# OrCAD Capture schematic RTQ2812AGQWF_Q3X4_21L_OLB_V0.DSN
size A2; note: Edison; note: RTQ2820_Q3X4_21L_ENG_V0
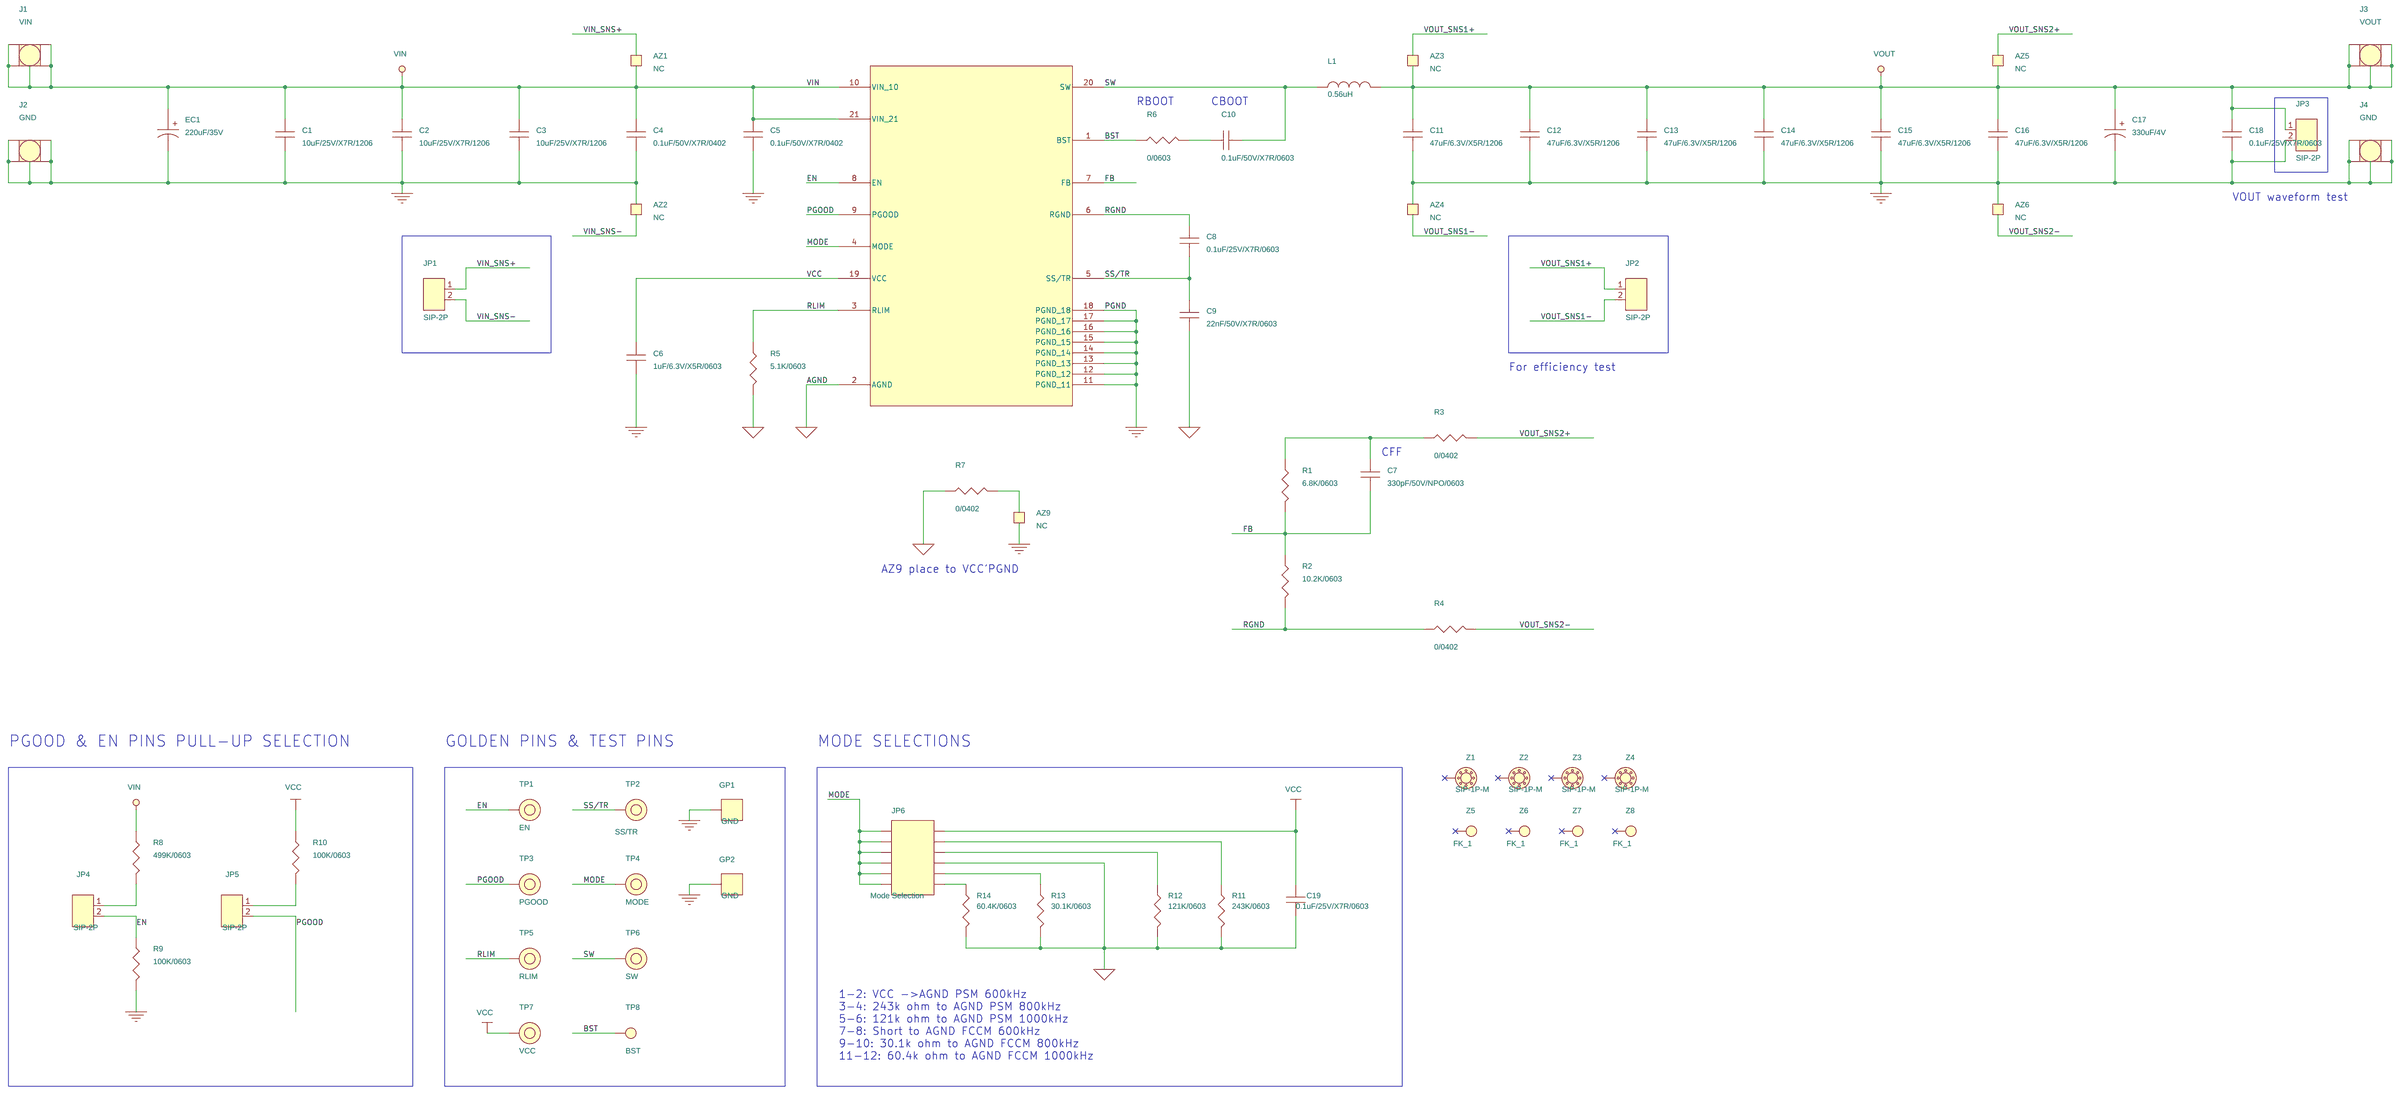
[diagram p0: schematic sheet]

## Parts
AZ1  NC  [nc-short10x30mil]
AZ2  NC  [nc-short10x30mil]
AZ3  NC  [nc-short10x30mil]
AZ4  NC  [nc-short10x30mil]
AZ5  NC  [nc-short10x30mil]
AZ6  NC  [nc-short10x30mil]
AZ9  NC  [nc-short10x30mil]
C1  10uF/25V/X7R/1206  [C-1206]
C2  10uF/25V/X7R/1206  [C-1206]
C3  10uF/25V/X7R/1206  [C-1206]
C4  0.1uF/50V/X7R/0402  [C-0402]
C5  0.1uF/50V/X7R/0402  [C-0402]
C6  1uF/6.3V/X5R/0603  [C-0603]
C7  330pF/50V/NPO/0603  [C-0603]
C8  0.1uF/25V/X7R/0603  [C-0603]
C9  22nF/50V/X7R/0603  [C-0603]
C10  0.1uF/50V/X7R/0603  [C-0603]
C11  47uF/6.3V/X5R/1206  [C-1206]
C12  47uF/6.3V/X5R/1206  [C-1206]
C13  47uF/6.3V/X5R/1206  [C-1206]
C14  47uF/6.3V/X5R/1206  [C-1206]
C15  47uF/6.3V/X5R/1206  [C-1206]
C16  47uF/6.3V/X5R/1206  [C-1206]
C17  330uF/4V  [c-1206-d3]
C18  0.1uF/25V/X7R/0603  [C-0603]
C19  0.1uF/25V/X7R/0603  [C-0603]
EC1  220uF/35V  [EC-2P_10_5MM]
GP1  GND  [SIP-1P-GP]
GP2  GND  [SIP-1P-GP]
J1  VIN  [SIP-5P_PW_L]
J2  GND  [SIP-5P_PW_L]
J3  VOUT  [SIP-5P_PW_L]
J4  GND  [SIP-5P_PW_L]
JP1  SIP-2P  [SIP-2P]
JP2  SIP-2P  [SIP-2P]
JP3  SIP-2P  [SIP-2P]
JP4  SIP-2P  [SIP-2P]
JP5  SIP-2P  [SIP-2P]
JP6  Mode Selection  [HEADER6X2]
L1  0.56uH  [L-11-5X10]
R1  6.8K/0603  [R-0603]
R2  10.2K/0603  [R-0603]
R3  0/0402  [R-0402]
R4  0/0402  [R-0402]
R5  5.1K/0603  [R-0603]
R6  0/0603  [R-0603]
R7  0/0402  [R-0402]
R8  499K/0603  [R-0603]
R9  100K/0603  [R-0603]
R10  100K/0603  [R-0603]
R11  243K/0603  [R-0603]
R12  121K/0603  [R-0603]
R13  30.1K/0603  [R-0603]
R14  60.4K/0603  [R-0603]
TP1  EN  [SIP-1P-TP]
TP2  SS/TR  [SIP-1P-TP]
TP3  PGOOD  [SIP-1P-TP]
TP4  MODE  [SIP-1P-TP]
TP5  RLIM  [SIP-1P-TP]
TP6  SW  [SIP-1P-TP]
TP7  VCC  [SIP-1P-TP]
TP8  BST  [FK_1]
U1  IC-4X2  [qfn3x4_21l_mpq8634a_moq8633b]
Z1  SIP-1P-M  [SIP-1P-M]
Z2  SIP-1P-M  [SIP-1P-M]
Z3  SIP-1P-M  [SIP-1P-M]
Z4  SIP-1P-M  [SIP-1P-M]
Z5  FK_1  [FK_1]
Z6  FK_1  [FK_1]
Z7  FK_1  [FK_1]
Z8  FK_1  [FK_1]

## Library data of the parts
AZ1-AZ6 AZ9 = T_POINT_S: Short Pin 10X30mil; currency: NTD; maker_part_number: NC-SHORT_10X30MIL; notes: S1_IAD1; package: 10X30mil; part_number: NC-SHORT_10X30MIL; part_type: SHORT; price: 0; Datasheet: IO.pdf
C1-C3 = CAP: CAP CER 10uF 25V X7R 1206; FPLIST: C-1206,N_C1206_INTEL,C-1206_INTEL,C-1206_AD; currency: USD; maker: TAIYO YUDEN; maker_part_number: TMK316AB7106KL-T; notes: E1_IAD1; package: 1206; part_number: TMK316AB7106KL-T; part_type: Ceramic; price: 0.0294; size: 3.20X1.60X0.95 mm; Datasheet: TMK316AB7106KL-T.pdf
C4 C5 = CAP: CAP CER 0.1uF(100nF)50V X7R 0402; FPLIST: C-0402,C0402,C-0402_ADPS; currency: USD; maker: WALSIN; maker_part_number: 0402B104K500CT; notes: E1_IAD1_WALSIN-0402B104K500CT; package: 0402; part_number: 0402B104K500CT; part_type: Ceramic; price: 0.0048; size: 1.00x0.50x0.55 mm; Datasheet: 0402B104K500CT.pdf
C6 = CAP: CAP CER 1uF 6.3V X5R 0603; FPLIST: C-0603,N_C0603_INTEL,C-0603_INTEL,C-0603_AD,0603C,C-0603_ADPS; currency: NTD; maker: MURATA; maker_part_number: GRM188R60J105KA01D; notes: C1_IAD1; package: 0603; part_number: GRM188R60J105KA01D; part_type: Ceramic; price: 5; size: 1.60X0.80X0.80mm; specific_part_bu: Specific-CP; supplier: NA; vendor: NA; Datasheet: cap_0603_1uF6.3V.pdf
C7 = CAP: 0603 NPO 330pF 50V; FPLIST: C-0603,N_C0603_INTEL,C-0603_INTEL,C-0603_AD,0603C,C-0603_ADPS; currency: USD; maker: WALSIN; maker_part_number: 0603N331J500CT; notes: E1_IAD1_Old:0603N331J500LT; package: 0603; part_number: 0603N331J500CT; part_type: Ceramic; price: 0.001800; size: 1.60x0.80x0.87 mm; Datasheet: ASC_General_Purpose.pdf
C8 C19 = CAP: CAP CER 0.1uF 25V X7R 0603; FPLIST: C-0603,N_C0603_INTEL,C-0603_INTEL,C-0603_AD,0603C; currency: USD; maker: WALSIN; maker_part_number: 0603B104K250CT; notes: E1_IAD1_WALSIN-0603B104K250CT=> Suggest using the  0402B104K250CT; package: 0603; part_number: 0603B104K250CT; part_type: Ceramic; price: 0.0019; size: 1.60x0.80x0.80 mm; specific_part_bu: Specific; Datasheet: 0603B104K250CT.pdf
C9 = CAP: CAP CER 22nF/50V/X7R/0603; FPLIST: C-0603,N_C0603_INTEL,C-0603_INTEL,C-0603_AD,0603C,C-0603_ADPS; currency: USD; maker: MURATA; maker_part_number: GRM188R71H223KA01D; notes: C1_IAD1_Suggest using alternative matericals-GRM155R71H223KA12D; package: 0603; part_number: GRM188R71H223KA01D; part_type: Ceramic; price: 0.003; size: 1.60x0.80x0.80 mm; supplier: MURATA; vendor: MURATA; Datasheet: GRM188R71H223KA01D.pdf
C10 = CAP: CAP CER 0.1uF 50V X7R 0603; FPLIST: C-0603,N_C0603_INTEL,C-0603_INTEL,C-0603_AD,0603C,C-0603_ADPS; currency: USD; maker: MURATA; maker_part_number: GRM188R71H104KA93D; notes: C1_IAD1_WALSIN-0603B104K500CT=>???0402B104K500CT; package: 0603; part_number: GRM188R71H104KA93D; part_type: Ceramic; price: 0.0048; size: 1.60x0.80x0.80 mm; Datasheet: GRM188R71H104KA93D.pdf
C11-C16 = CAP: CAP CER 47uF 6.3V X5R 1206; FPLIST: C-1206,N_C1206_INTEL,C-1206_INTEL,C-1206_AD,C-1206-D3; currency: USD; maker: TDK; maker_part_number: C3216X5R0J476M160AC; notes: S1_IAD1_EOL,P/N is corresponding for WALSIN-1206X476M6R3CT-USD-0.03240-1KK BOM COST; package: 1206; part_number: C3216X5R0J476M160AC; part_type: Ceramic; price: 0.03240; size: 3.20x1.60x1.60 mm; Datasheet: mlcc_commercial_general_en.pdf
C17 = CAP-POL: Polymer Alum Cap 330uF 20% 4V; currency: NTD; maker: PANASONIC; maker_part_number: EEFSX0G331ER; notes: E1_IAD1_Free_Sample; package: SP-CAP; part_number: EEFSX0G331ER; part_type: POS; price: 0; size: 7.30x4.30x1.90 mm; specific_part_bu: Specific-CP; Datasheet: EEFSX0G331ER.pdf
C18 = CAP: CAP, CERM, 0.1uF, 25V, +/- 10%, X7R,0603; FPLIST: C-0603,N_C0603_INTEL,C-0603_INTEL,C-0603_AD,0603C; currency: NTD; maker: MURATA; maker_part_number: GRM188R71E104KA01D; notes: C1_IAD1; package: 0603; part_number: GRM188R71E104KA01D; part_type: Ceramic; price: 0.01; size: 1.6X0.8X0.8 mm; specific_part_bu: Specific-MB; Datasheet: GRM188R71E104KA01-01.pdf
EC1 = CAP-POL: E CAP ALUM 220uF 20% 35V RADIAL; currency: NTD; maker: RUBYCON; maker_part_number: 35YXG220MEFC10X12.5; notes: E1_IAD1; package: radial_direction; part_number: 35YXG220MEFC10X12.5; part_type: Aluminum; price: 1.6; size: 10.00x12.50/5.00 mm; Datasheet: e_YXG.pdf
GP1 GP2 = SIP-1P-GP: Gold Pin; currency: NTD; maker: BO-JIANG; maker_part_number: GOLD PIN; notes: S1_IAD1; part_number: IO-1; part_type: IO; price: 2; Datasheet: BO-JIANG_Gold Pin.pdf
J1-J4 = SIP-5P_PW_L: notes: E1_IAD1_added for TC0647_D3_10L_V0; package: Co-Lay Screw Hole and Connector; part_number: IO-90; part_type: IO; Datasheet: JH-4L-CXS.pdf
JP1-JP5 = SIP-2P: 2.54mm SIP Socket Round Single Series(2pin); currency: NTD; maker: CHERNG WEEI; maker_part_number: CSIP25401x02-CF787; notes: E1_IAD1; part_number: CSIP25401x02-CF787; part_type: IO; price: 0.92; specific_part_bu: Spectific-RDC; Datasheet: CSIP25401x__-CF787.pdf
JP6 = HEADER6X2: 2.54mm HEADER6X2; currency: NTD; maker: CHERNG WEEI; notes: A1_IAD1; part_number: IO-59; part_type: IO; price: 4.7; Datasheet: HEADER-P201-SG_-060_030-XX.pdf
L1 = INDUCTOR: FIXED IND 0.56uH 30A 1.56mOHM SMD; currency: NTD; maker: PANASONIC; maker_part_number: ETQP4LR56WFC; notes: C1_CAAD1; part_number: ETQP4LR56WFC; part_type: Inductor; price: 5.5; size: 11.5⊙10.0⊙4.0 mm; specific_part_bu: Specific; tolerance: ∮20%; Datasheet: ETQP4L.pdf
R1 = R: RES SMD 6.8K OHM 1% 1/10W 0603; FPLIST: R-0603,N_R0603_INTEL,R-0603_INTEL,R-0603_AD,0603R; currency: USD; maker: WALSIN; maker_part_number: WR06X6801FTL; notes: IAD1_E1; package: 0603; part_number: WR06X6801FTL; part_type: CHIP R; price: 0.0038; size: 1.60x0.80x0.45 mm; Datasheet: ASC_WR.pdf
R2 = R: RES SMD 10K2 1% 1/10W 0603; FPLIST: R-0603,N_R0603_INTEL,R-0603_INTEL,R-0603_AD,0603R; currency: NTD; maker: EVER OHMS; maker_part_number: CR0603F10K2P05Z; notes: A1_IAD1_P/N is correspongding for RALEC:RTT031022FTP; package: 0603; part_number: CR0603F10K2P05Z; part_type: CHIP R; price: 0.013; size: 1.60x0.80x0.40 mm; supplier: EVER OHMS; vendor: EVER OHMS; Datasheet: CR_series.pdf
R3 R4 R7 = R: RES SMD 0 OHM Jumper 1/16W 0402; FPLIST: R-0402,R0402,R-0402_ADPS,R-0402_I; currency: USD; maker: WALSIN; maker_part_number: WR04X000 PTL; notes: A1_IAD1_Old:WR04X000PTL; package: 0402; part_number: WR04X000 PTL; part_type: CHIP R; price: 0.00026; size: 1.00x0.50x0.35 mm; Datasheet: ASC_WR.pdf
R5 = R: RES SMD 5K1 1% 1/10W 0603; FPLIST: R-0603,N_R0603_INTEL,R-0603_INTEL,R-0603_AD,0603R; currency: USD; maker: YAGEO; maker_part_number: RC0603FR-075K1L; notes: A1_IAD1; package: 0603; part_number: RC0603FR-075K1L; part_type: CHIP R; price: 0.001515; size: 1.60x0.80x0.45 mm; Datasheet: PYu-RC_Group_51_RoHS.pdf
R6 = R: RES SMD 0 OHM Jumper 1/10W 0603 5%; FPLIST: R-0603,N_R0603_INTEL,R-0603_INTEL,R-0603_AD,0603R,R-0603_ADPS; currency: USD; maker: WALSIN; maker_part_number: WR06X000 PTL; notes: S1_IAD1_Old:WR06X000PTL; package: 0603; part_number: WR06X000PTL; part_type: CHIP R; price: 0.00045; size: 1.60x0.80x0.45 mm; Datasheet: ASC_WR.pdf
R8 = R: RES SMD 499K OHM 1% 1/10W 0603; FPLIST: R-0603,N_R0603_INTEL,R-0603_INTEL,R-0603_AD,0603R,R-0603_ADPS; currency: USD; maker: WALSIN; maker_part_number: WR06X4993FTL; notes: IAD1_C1; package: 0603; part_number: WR06X4993FTL; part_type: CHIP R; price: 0.0038; size: 1.60x0.80x0.45 mm; Datasheet: ASC_WR.pdf
R9 R10 = R: RES SMD 100K OHM 1% 1/10W 0603; FPLIST: R-0603,N_R0603_INTEL,R-0603_INTEL,R-0603_AD,0603R; currency: USD; maker: WALSIN; maker_part_number: WR06X1003FTL; notes: S1_IAD1; package: 0603; part_number: WR06X1003FTL; part_type: CHIP R; price: 0.0038; size: 1.60x0.80x0.45 mm; Datasheet: ASC_WR.pdf
R11 = R: RES SMD 243K OHM 1% 1/10W 0603; FPLIST: R-0603,N_R0603_INTEL,R-0603_INTEL,R-0603_AD,0603R; currency: USD; maker: WALSIN; maker_part_number: WR06X2433FTL; notes: S1_IAD1; package: 0603; part_number: WR06X2433FTL; part_type: CHIP R; price: 0.0038; size: 1.60x0.80x0.45 mm; Datasheet: ASC_WR.pdf
R12 = R: RES SMD 121K OHM 1% 1/10W 0603; FPLIST: R-0603,N_R0603_INTEL,R-0603_INTEL,R-0603_AD,0603R; currency: NTD; maker: RALEC; maker_part_number: RTT031213FTP; notes: A1_IAD1_Reference price; package: 0603; part_number: RTT031213FTP; part_type: CHIP R; price: 0.03; size: 1.60x0.80x0.45 mm; Datasheet: RTT (2016.07.25).pdf
R13 = R: RES SMD 30.1K OHM 1% 1/10W 0603; FPLIST: R-0603,N_R0603_INTEL,R-0603_INTEL,R-0603_AD,0603R; currency: USD; maker: RALEC; maker_part_number: RTT033012FTP; notes: E1_IAD1; package: 0603; part_number: RTT033012FTP; part_type: CHIP R; size: 1.60x0.80x0.45 mm; Datasheet: RTT (2016.07.25).pdf
R14 = R: RES SMD 60K4 1% 1/10W 0603; FPLIST: R-0603,N_R0603_INTEL,R-0603_INTEL,R-0603_AD,0603R; currency: NTD; maker: EVER OHMS; maker_part_number: CR0603F60K4P05Z; notes: A1_IAD1_P/N is correspongding for RALEC:RTT036042FTP; package: 0603; part_number: CR0603F60K4P05Z; part_type: CHIP R; price: 0.013; size: 1.60x0.80x0.40 mm; supplier: EVER OHMS; vendor: EVER OHMS; Datasheet: CR_series.pdf
TP1-TP7 = SIP-1P-TP: Test Pin; currency: NTD; maker: PINGOOD; notes: S1_IAD1; part_number: IO-2; part_type: IO; price: 1.5; Datasheet: JT-1P-CIL.pdf
TP8 Z5-Z8 = FK_1: Fiducial Mark; notes: S1_IAD1; part_number: IO-7; part_type: IO; Datasheet: FK_1.pdf
U1 = IC-4X2_90
Z1-Z4 = SIP-1P-M: P.C.B. spacer support; currency: NTD; maker: PINGOOD; maker_part_number: TCK-17; notes: S1_IAD1; part_number: IO-4; part_type: IO; price: 0.9; Datasheet: TCK-17.pdf

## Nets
GND: AZ2.1 AZ4.1 AZ6.1 AZ9.2 C1.2 C2.2 C3.2 C4.2 C5.2 C6.2 C11.2 C12.2 C13.2 C14.2 C15.2 C16.2 C17.2 C18.2 EC1.2 GP1.1 GP2.1 J2.1 J2.2 J2.3 J2.4 J2.5 J4.1 J4.2 J4.3 J4.4 J4.5 JP3.2 R9.2 U1.11(PGND) U1.12(PGND) U1.13(PGND) U1.14(PGND) U1.15(PGND) U1.16(PGND) U1.17(PGND) U1.18(PGND)
GND_SIGNAL: C9.2 C19.2 JP6.8 R5.2 R7.1 R11.2 R12.2 R13.2 R14.2 U1.2(AGND)
VCC: C6.1 C19.1 JP6.2 R10.1 TP7.1 U1.19(VCC)
VIN: AZ1.2 C1.1 C2.1 C3.1 C4.1 C5.1 EC1.1 J1.1 J1.2 J1.3 J1.4 J1.5 R8.1 U1.10(VIN) U1.21(VIN)
VIN_SNS+: AZ1.1 JP1.1
VIN_SNS-: AZ2.2 JP1.2
BST: R6.1 TP8.1 U1.1(BST)
EN: JP4.2 R9.1 TP1.1 U1.8(EN)
FB: C7.2 R1.2 R2.1 U1.7(FB)
MODE: JP6.1 JP6.3 JP6.5 JP6.7 JP6.9 JP6.11 TP4.1 U1.4(MODE)
PGOOD: JP5.2 TP3.1 U1.9(PGOOD)
RGND: C8.1 R2.2 R4.1 U1.6(RGND)
RLIM: R5.1 TP5.1 U1.3(RLIM)
SS/TR: C8.2 C9.1 TP2.1 U1.5(SS/TR)
SW: C10.2 L1.1 TP6.1 U1.20(SW)
VOUT: AZ3.2 AZ5.2 C11.1 C12.1 C13.1 C14.1 C15.1 C16.1 C17.1 C18.1 J3.1 J3.2 J3.3 J3.4 J3.5 JP3.1 L1.2
VOUT_SNS1+: AZ3.1 JP2.1
VOUT_SNS1-: AZ4.2 JP2.2
VOUT_SNS2+: AZ5.1 R3.2
VOUT_SNS2-: AZ6.2 R4.2
N13867294: AZ9.1 R7.2
N13940700: C7.1 R1.1 R3.1
N14132389: JP6.12 R14.1
N14132862: JP6.10 R13.1
N14133010: JP6.4 R11.1
N14133662: JP6.6 R12.1
N14144379: JP5.1 R10.2
N14155202: JP4.1 R8.2
N14190589: C10.1 R6.2

Not connected (* = marked no-connect by the designer): Z1 1*; Z2 1*; Z3 1*; Z4 1*; Z5 1*; Z6 1*; Z7 1*; Z8 1*

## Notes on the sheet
- RBOOT
- CBOOT
- VOUT waveform test
- For efficiency test
- CFF
- AZ9 place to VCC'PGND
- PGOOD & EN PINS PULL-UP SELECTION
- GOLDEN PINS & TEST PINS
- MODE SELECTIONS
- 1-2: VCC ->AGND PSM 600kHz
  3-4: 243k ohm to AGND PSM 800kHz
  5-6: 121k ohm to AGND PSM 1000kHz
  7-8: Short to AGND FCCM 600kHz
  9-10: 30.1k ohm to AGND FCCM 800kHz
  11-12: 60.4k ohm to AGND FCCM 1000kHz
